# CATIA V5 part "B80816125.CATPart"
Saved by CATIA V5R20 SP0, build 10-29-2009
Part number: B80816125
Revision: 3
Definition: design
Nomenclature: B80816125
Source: made
Description: NOT SPECIFIED
Bounding box of the stored display mesh (mm): x -10 to 10, y -10 to 10, z 0 to 125
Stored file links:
  C:\Users\Raffaele\Desktop\3D X SITO CF\BOLEX\4-PILLAR REF 808\B80816125.CATPart
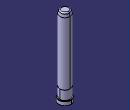
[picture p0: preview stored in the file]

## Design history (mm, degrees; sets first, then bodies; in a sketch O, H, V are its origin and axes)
Body1 "MANIFOLD_SOLID_BREP #450" (main body)
  Solid1: solid without history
